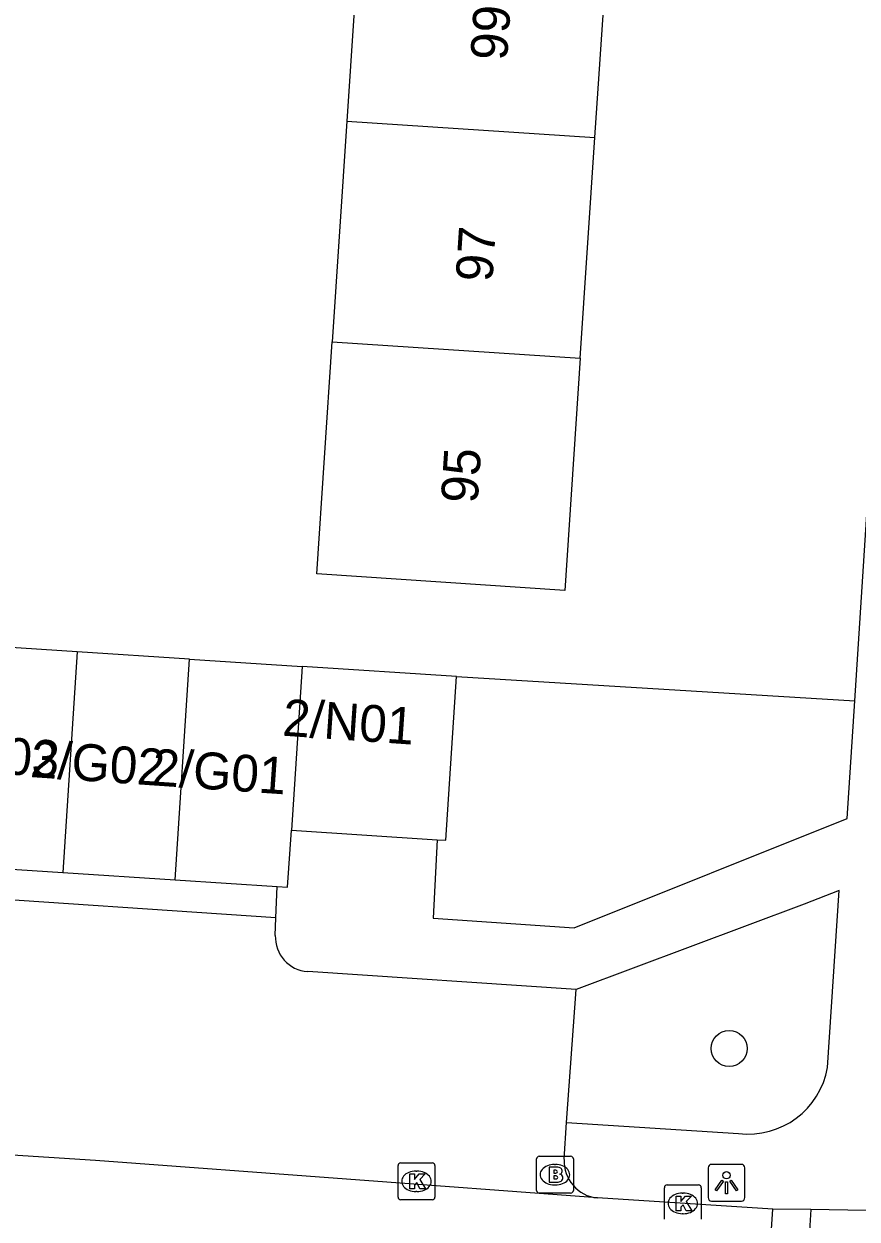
# Model space of a CAD drawing. Extents: x 161848 to 162726, y 385382 to 386521.
# Drawn here: x 162011.4 to 162034.02, y 386136.8 to 386169.24 of the extents above; entities that cross this region are included whole.
import ezdxf

# ---------------------------------------------------------------- set-up
doc = ezdxf.new("R2010")
doc.units = 0
for name, color, linetype in [('IMGEO_Boom', 7, 'Continuous'), ('IMGEO_Brandkraan', 7, 'Continuous'), ('IMGEO_Groenvoorziening', 7, 'Continuous'), ('IMGEO_Hek', 7, 'Continuous'), ('IMGEO_Kolk', 7, 'Continuous'), ('IMGEO_Lichtpunt', 7, 'Continuous'), ('IMGEO_Pand', 7, 'Continuous'), ('IMGEO_Pand_nummerreeks', 7, 'Continuous'), ('IMGEO_Parkeervlak_open', 7, 'Continuous'), ('IMGEO_Rijbaan_lokaal_open', 7, 'Continuous'), ('IMGEO_Voetpad_open', 7, 'Continuous')]:
    doc.layers.add(name, color=color, linetype=linetype)

msp = doc.modelspace()

# ---------------------------------------------------------------- linework, layer by layer
at = {"layer": 'IMGEO_Boom'}
msp.add_circle((162030.544, 386141.432), 0.489, dxfattribs=at)
at = {"layer": 'IMGEO_Brandkraan'}
for p, q in [((162025.312, 386137.579), (162025.312, 386138.431)), ((162025.387, 386138.505), (162026.239, 386138.505)), ((162026.313, 386138.431), (162026.313, 386137.579)), ((162025.8, 386138.285), (162025.825, 386138.285)), ((162025.823, 386137.725), (162025.798, 386137.725)), ((162026.239, 386137.505), (162025.387, 386137.505))]:
    msp.add_line(p, q, dxfattribs=at)
for points in [[(162025.312, 386137.579), (162025.312, 386138.431)], [(162025.387, 386138.505), (162026.239, 386138.505)], [(162026.313, 386138.431), (162026.313, 386137.579)], [(162025.66, 386138.205), (162025.66, 386137.805), (162025.873, 386137.805)], [(162025.891, 386138.205), (162025.66, 386138.205)], [(162025.839, 386138.124), (162025.785, 386138.124), (162025.785, 386138.048)], [(162025.785, 386138.048), (162025.838, 386138.048)], [(162025.847, 386137.972), (162025.785, 386137.972), (162025.785, 386137.891)], [(162025.785, 386137.891), (162025.847, 386137.891)], [(162026.239, 386137.505), (162025.387, 386137.505)]]:
    msp.add_lwpolyline(points, dxfattribs=at)
for centre, radius, start, end in [((162025.389, 386138.429), 0.0765, 91.552, 178.448), ((162025.389, 386138.429), 0.0765, 91.552, 178.448), ((162026.237, 386138.429), 0.0765, 1.552, 88.448), ((162026.237, 386138.429), 0.0765, 1.552, 88.448), ((162025.84, 386138.086), 0.0379, 267.8285, 90.9355), ((162025.895, 386138.06), 0.145, 59.4692, 91.5367), ((162025.92, 386138.107), 0.0922, 285.5137, 58.1501), ((162025.848, 386137.931), 0.0404, 269.8759, 90.5077), ((162025.879, 386138.056), 0.251, 268.6676, 293.5347), ((162025.925, 386137.915), 0.105, 301.3115, 78.989), ((162025.389, 386137.581), 0.0765, 181.552, 268.448), ((162025.389, 386137.581), 0.0765, 181.552, 268.448), ((162026.237, 386137.581), 0.0765, 271.552, 358.448), ((162026.237, 386137.581), 0.0765, 271.552, 358.448)]:
    msp.add_arc(centre, radius, start, end, dxfattribs=at)
for centre, major_axis, ratio, start_param, end_param in [((162025.799, 386138.005), (-0.387, 0.002), 0.722429, 4.712389, 7.853982), ((162025.824, 386138.005), (-0.39, 0.002), 0.717154, 1.570796, 4.712389)]:
    msp.add_ellipse(centre, major_axis=major_axis, ratio=ratio, start_param=start_param, end_param=end_param, dxfattribs=at)
at = {"layer": 'IMGEO_Groenvoorziening'}
msp.add_lwpolyline([(162023.139, 386151.525), (162033.95, 386150.87)], dxfattribs=at)
at = {"layer": 'IMGEO_Hek'}
msp.add_lwpolyline([(162023.139, 386151.525), (162033.95, 386150.87)], dxfattribs=at)
at = {"layer": 'IMGEO_Kolk'}
for p, q in [((162021.553, 386137.399), (162021.553, 386138.251)), ((162021.628, 386138.325), (162022.48, 386138.325)), ((162022.041, 386138.105), (162022.066, 386138.105)), ((162022.554, 386138.251), (162022.554, 386137.399)), ((162028.858, 386137.726), (162029.71, 386137.726)), ((162022.064, 386137.545), (162022.039, 386137.545)), ((162028.783, 386136.8), (162028.783, 386137.652)), ((162029.271, 386137.506), (162029.296, 386137.506)), ((162029.784, 386137.652), (162029.784, 386136.8)), ((162022.48, 386137.325), (162021.628, 386137.325)), ((162029.294, 386136.946), (162029.269, 386136.946))]:
    msp.add_line(p, q, dxfattribs=at)
for points in [[(162021.553, 386137.399), (162021.553, 386138.251)], [(162021.628, 386138.325), (162022.48, 386138.325)], [(162021.874, 386138.025), (162021.997, 386138.025), (162021.997, 386137.874), (162022.127, 386138.025), (162022.291, 386138.025), (162022.145, 386137.874), (162022.298, 386137.625), (162022.146, 386137.625), (162022.061, 386137.789), (162021.997, 386137.722), (162021.997, 386137.625), (162021.874, 386137.625), (162021.874, 386138.025)], [(162022.554, 386138.251), (162022.554, 386137.399)], [(162028.858, 386137.726), (162029.71, 386137.726)], [(162028.783, 386136.8), (162028.783, 386137.652)], [(162029.104, 386137.426), (162029.227, 386137.426), (162029.227, 386137.275), (162029.357, 386137.426), (162029.521, 386137.426), (162029.375, 386137.275), (162029.528, 386137.026), (162029.376, 386137.026), (162029.291, 386137.19), (162029.227, 386137.123), (162029.227, 386137.026), (162029.104, 386137.026), (162029.104, 386137.426)], [(162029.784, 386137.652), (162029.784, 386136.8)], [(162022.48, 386137.325), (162021.628, 386137.325)]]:
    msp.add_lwpolyline(points, dxfattribs=at)
for centre, start, end in [((162021.63, 386138.249), 91.552, 178.448), ((162021.63, 386138.249), 91.552, 178.448), ((162022.478, 386138.249), 1.552, 88.448), ((162022.478, 386138.249), 1.552, 88.448), ((162028.86, 386137.65), 91.552, 178.448), ((162028.86, 386137.65), 91.552, 178.448), ((162029.708, 386137.65), 1.552, 88.448), ((162029.708, 386137.65), 1.552, 88.448), ((162021.63, 386137.401), 181.552, 268.448), ((162021.63, 386137.401), 181.552, 268.448), ((162022.478, 386137.401), 271.552, 358.448), ((162022.478, 386137.401), 271.552, 358.448)]:
    msp.add_arc(centre, 0.0765, start, end, dxfattribs=at)
for centre, major_axis, ratio, start_param, end_param in [((162022.04, 386137.825), (-0.387, 0.002), 0.722429, 4.712389, 7.853982), ((162022.065, 386137.825), (-0.39, 0.002), 0.717154, 1.570796, 4.712389), ((162029.27, 386137.226), (-0.387, 0.002), 0.722429, 4.712389, 7.853982), ((162029.295, 386137.226), (-0.39, 0.002), 0.717154, 1.570796, 4.712389)]:
    msp.add_ellipse(centre, major_axis=major_axis, ratio=ratio, start_param=start_param, end_param=end_param, dxfattribs=at)
at = {"layer": 'IMGEO_Lichtpunt'}
for p, q in [((162029.971, 386138.191), (162029.971, 386137.384)), ((162029.971, 386138.191), (162029.971, 386137.384)), ((162030.873, 386138.286), (162030.065, 386138.286)), ((162030.873, 386138.286), (162030.065, 386138.286)), ((162030.967, 386137.384), (162030.967, 386138.191)), ((162030.967, 386137.384), (162030.967, 386138.191)), ((162030.065, 386137.29), (162030.873, 386137.29)), ((162030.065, 386137.29), (162030.873, 386137.29))]:
    msp.add_line(p, q, dxfattribs=at)
for points in [[(162030.345, 386137.855), (162030.384, 386137.827), (162030.196, 386137.565), (162030.158, 386137.592), (162030.345, 386137.855)], [(162030.447, 386137.807), (162030.494, 386137.807), (162030.494, 386137.485), (162030.447, 386137.485), (162030.447, 386137.807)], [(162030.557, 386137.827), (162030.595, 386137.854), (162030.782, 386137.592), (162030.743, 386137.564), (162030.557, 386137.827)]]:
    msp.add_lwpolyline(points, dxfattribs=at)
msp.add_circle((162030.47, 386137.989), 0.0994, dxfattribs=at)
for centre, start, end in [((162030.065, 386138.191), 90, 180), ((162030.065, 386138.191), 90, 180), ((162030.873, 386138.191), 0, 90), ((162030.873, 386138.191), 0, 90), ((162030.065, 386137.384), 180, 270), ((162030.065, 386137.384), 180, 270), ((162030.873, 386137.384), 270, 0), ((162030.873, 386137.384), 270, 360)]:
    msp.add_arc(centre, 0.0946, start, end, dxfattribs=at)
at = {"layer": 'IMGEO_Pand'}
for points in [[(162020.564, 386172.593), (162020.165, 386166.601)], [(162026.9, 386166.154), (162027.299, 386172.146)], [(162020.165, 386166.601), (162019.766, 386160.609)], [(162020.165, 386166.601), (162026.9, 386166.154)], [(162026.501, 386160.162), (162026.9, 386166.154)], [(162026.501, 386160.162), (162026.082, 386153.86), (162019.347, 386154.309), (162019.766, 386160.609)], [(162019.766, 386160.609), (162026.501, 386160.162)], [(162012.842, 386152.199), (162009.79, 386152.398)], [(162012.842, 386152.199), (162012.451, 386146.211)], [(162015.895, 386151.999), (162012.842, 386152.199)], [(162015.503, 386146.011), (162015.895, 386151.999)], [(162015.895, 386151.999), (162018.948, 386151.799)], [(162018.948, 386151.799), (162018.657, 386147.354)], [(162023.139, 386151.525), (162018.948, 386151.799)], [(162022.617, 386147.095), (162022.849, 386147.08), (162023.139, 386151.525)], [(162018.272, 386145.83), (162018.556, 386145.811), (162018.657, 386147.354)], [(162018.657, 386147.354), (162022.617, 386147.095)], [(162009.398, 386146.41), (162012.451, 386146.211)], [(162012.451, 386146.211), (162015.503, 386146.011)], [(162015.503, 386146.011), (162018.272, 386145.83)]]:
    msp.add_lwpolyline(points, dxfattribs=at)
at = {"layer": 'IMGEO_Parkeervlak_open'}
msp.add_lwpolyline([(162026.131, 386139.418), (162026.393, 386143.034)], dxfattribs=at)
at = {"layer": 'IMGEO_Rijbaan_lokaal_open'}
for points in [[(162026.967, 386137.373), (162013.34, 386138.388), (161981.65, 386140.427)], [(162031.725, 386137.072), (162026.967, 386137.373)], [(162031.397, 386132.045), (162031.725, 386137.072)], [(162032.762, 386137.056), (162032.445, 386131.997)], [(162034.263, 386137.033), (162032.762, 386137.056)]]:
    msp.add_lwpolyline(points, dxfattribs=at)
at = {"layer": 'IMGEO_Voetpad_open'}
for points in [[(162033.95, 386150.87), (162035.725, 386178.438), (162037.376, 386203.429), (162038.844, 386225.482)], [(162022.617, 386147.095), (162022.508, 386144.968), (162026.335, 386144.705), (162033.744, 386147.673), (162033.95, 386150.87)], [(162018.24, 386144.977), (162000, 386146.203), (161983.794, 386147.293)], [(162018.24, 386144.977), (162018.272, 386145.83)], [(162033.212, 386140.917), (162033.532, 386145.721), (162032.574, 386145.345), (162026.393, 386143.034)], [(162018.222, 386144.5), (162018.24, 386144.977)], [(162026.393, 386143.034), (162019.102, 386143.517)], [(162026.059, 386138.422), (162026.131, 386139.418)], [(162026.131, 386139.418), (162030.799, 386139.125)], [(162032.762, 386137.056), (162031.725, 386137.072)]]:
    msp.add_lwpolyline(points, dxfattribs=at)
for centre, radius, start, end in [((162019.169, 386144.462), 0.948, 177.7161, 265.9549), ((162031.066, 386141.286), 2.178, 262.9585, 350.24), ((162027.067, 386138.377), 1.009, 177.465, 264.2931)]:
    msp.add_arc(centre, radius, start, end, dxfattribs=at)

# ---------------------------------------------------------------- texts
at = {"layer": 'IMGEO_Pand_nummerreeks'}
for s, rotation, p in [('99', 86.192, (162024.512, 386168.228)), ('97', 86.192, (162024.112, 386162.218)), ('95', 86.192, (162023.712, 386156.208)), ('2/N01', 356.0468, (162018.398, 386149.922)), ('2/G03', 356.0966, (162008.693, 386149.027)), ('2/G02', 356.0966, (162011.551, 386148.799)), ('2/G01', 356.0966, (162014.851, 386148.574))]:
    msp.add_text(s, height=1, rotation=rotation, dxfattribs=at).set_placement(p)

doc.saveas('drawing.dxf')
